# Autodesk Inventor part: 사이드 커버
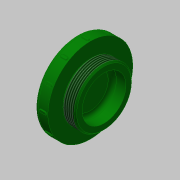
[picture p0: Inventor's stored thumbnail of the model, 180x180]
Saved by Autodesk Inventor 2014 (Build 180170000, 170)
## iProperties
Created: 2016-08
Part Number: 사이드 커버
Material: 스테인리스강
Document SubType Name: Modeling
Designer: mduedu
Density: 8.08 g/cm^3
Appearance: Dark Green
Author: mduedu
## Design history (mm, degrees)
sketch "스케치1"
  geometry: L1 (-5, 0)-(5, 0); L2 (-5, 0)-(-5, 31); L3 (-5, 31)-(5, 31); L4 (5, 31)-(5, 21); L5 (5, 21)-(15, 21); L6 (15, 21)-(15, 16); L7 (15, 16)-(5, 16); L8 (5, 16)-(5, 0); 2 further points
  constraints: 16 end point, 4 parallel, 2 perpendicular, 1 coincident, 1 collinear, 1 horizontal, 1 midpoint, 1 vertical
  dimensions: "d0" = 10 distance of L1.start L1.end; "d2" = 62 diameter of L3 L1; "d3" = 42 diameter of L5 L1; "d4" = 10 distance between parallel lines of L6 L8; "d5" = 5 distance of L5.end L6.end
revolve "회전1" sketch "스케치1" stored, may be unused: angle "d6" = 90 deg
fillet "모깎기1" dims "d7" = 3
sketch "스케치2"
  geometry: L1 (5, -31)-(5, 31) reference; L2 (5, 21)-(15, 21) reference; L3 (0, 0)-(5, 0); L4 (5, 21)-(6, 21); L5 (6, 21)-(6, 20); L6 (6, 20)-(5, 20); L7 (5, 20)-(5, 21)
  constraints: 10 end point, 2 parallel, 1 horizontal, 1 midpoint, 1 perpendicular
  dimensions: "d8" = 1 distance of L2.start L4.end; "d9" = 40 diameter of L6 L3
revolve "회전2" sketch "스케치2" stored, may be unused: angle "d10" = 90 deg
fillet "모깎기2" dims "d11" = 3
feature "스레드1" dims "d12" = 10, "d13" = 0
chamfer "모따기1" distance "d14" = 1; stored, may be unused: second distance "d15" = 2, angle "d16" = 45 deg
node "작업 평면1"
sketch "스케치3"
  geometry: L1 (1, -1)-(-4, -1); L2 (-4, -1)-(-4, 1); L3 (-4, 1)-(1, 1); L4 (1, 1)-(1, -1); 2 further points
  constraints: 8 end point, 2 parallel, 1 horizontal, 1 horizontal alignment, 1 midpoint, 1 perpendicular
  dimensions: "d18" = 2 distance of L3.end L1.start; "d20" = 5 distance of L1.start L1.end; "d21" = 1 distance from line of L4 point (0, 0)
extrude "돌출1" join sketch "스케치3" stored distance "d22" = 10; taper "d23" = 0 deg
fillet "모깎기3" dims "d24" = 1
fillet "모깎기4" dims "d25" = 0.2
sketch "스케치4"
  geometry: 2 further points
  constraints: 1 coincident, 1 other
feature "엠보싱1" sketch "스케치4" dims "d0" = 10, "d2" = 62, "d3" = 42, "d4" = 10, "d5" = 5, "d29" = 0.5, "d30" = 0
node "솔리드1"
pattern_circular "원형 패턴1" dims "d27" = 360 deg
other parameters: "d17" = 31.5
